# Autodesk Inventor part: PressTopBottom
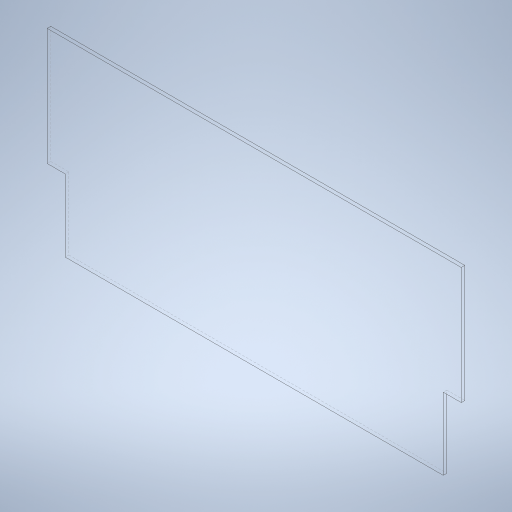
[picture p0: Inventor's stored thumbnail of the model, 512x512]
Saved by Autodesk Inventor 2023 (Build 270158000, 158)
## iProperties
Created: 2023-11
Part Number: PressTopBottom
Material: Generic
Document SubType Name: Modeling
Designer: tornqvih
Density: 1 g/cm^3
Appearance: Default
Author: tornqvih
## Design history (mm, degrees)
sketch "Sketch1"
  geometry: L1 (0, 0)-(230, 0); L2 (230, 0)-(230, -65); L3 (230, -65)-(220, -65); L4 (220, -65)-(220, -105); L5 (220, -105)-(10, -105); L6 (10, -105)-(10, -65); L7 (0, -65)-(0, 0); L8 (10, -65)-(0, -65); 1 further point
  constraints: 16 end point, 4 horizontal, 4 vertical, 1 coincident, 1 horizontal alignment
  dimensions: "d0" = 230 distance of L1.start L1.end; "d3" = 40 distance of L3.end L4.end; "d6" = 105 distance between parallel lines of L5 L1; "d7" = 10 distance of L6.end L7.start; "d8" = 10 distance of L2.end L3.end
extrude "Extrusion1" new body sketch "Sketch1" distance "d4" = 2; taper "d5" = 0 deg
body "Solid1"
